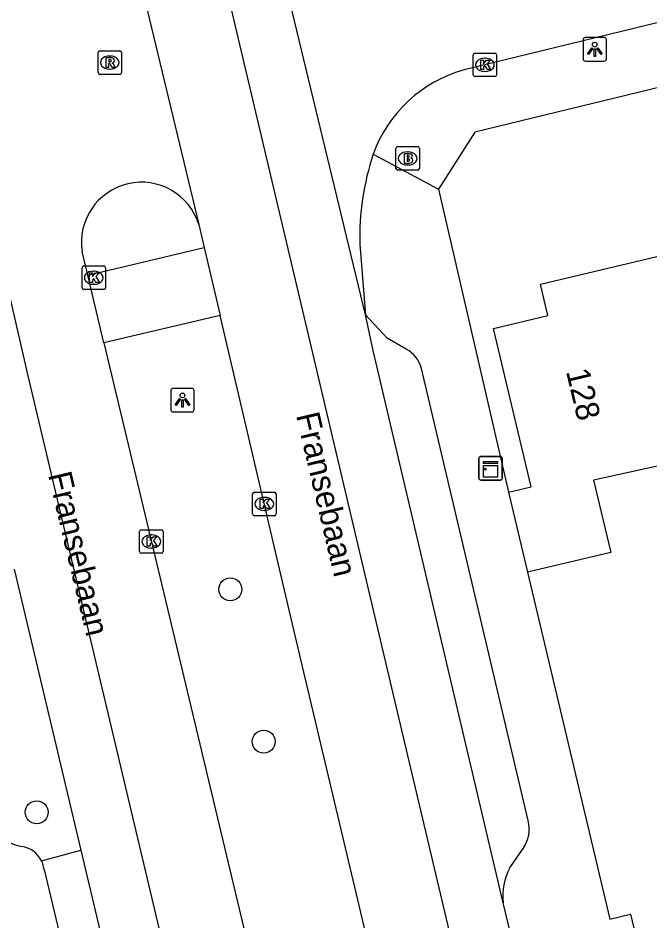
# Model space of a CAD drawing. Extents: x 158474 to 159560, y 388525 to 389605.
# Drawn here: x 159258.19 to 159285.1, y 388849.05 to 388887.46 of the extents above; entities that cross this region are included whole.
import ezdxf

# ---------------------------------------------------------------- set-up
doc = ezdxf.new("R2010")
doc.units = 0
for name, color, linetype in [('IMGEO_Boom', 7, 'Continuous'), ('IMGEO_Brandkraan', 7, 'Continuous'), ('IMGEO_Kast', 7, 'Continuous'), ('IMGEO_Kolk', 7, 'Continuous'), ('IMGEO_Lichtpunt', 7, 'Continuous'), ('IMGEO_Muur', 7, 'Continuous'), ('IMGEO_Openbare_ruimte_label', 7, 'Continuous'), ('IMGEO_Pand', 7, 'Continuous'), ('IMGEO_Pand_nummerreeks', 7, 'Continuous'), ('IMGEO_Rijbaan_lokaal_gesloten', 7, 'Continuous'), ('IMGEO_Rijbaan_lokaal_open', 7, 'Continuous'), ('IMGEO_Rioolput', 7, 'Continuous'), ('IMGEO_Verkeerseiland_groen', 7, 'Continuous'), ('IMGEO_Voetpad_open', 7, 'Continuous')]:
    doc.layers.add(name, color=color, linetype=linetype)

msp = doc.modelspace()

# ---------------------------------------------------------------- linework, layer by layer
at = {"layer": 'IMGEO_Boom'}
for centre in [(159267.227, 388863.157), (159268.651, 388856.68), (159258.987, 388853.674)]:
    msp.add_circle(centre, 0.489, dxfattribs=at)
at = {"layer": 'IMGEO_Brandkraan'}
for p, q in [((159274.282, 388881.066), (159274.282, 388881.918)), ((159274.357, 388881.992), (159275.209, 388881.992)), ((159275.283, 388881.918), (159275.283, 388881.066)), ((159274.77, 388881.772), (159274.795, 388881.772)), ((159274.793, 388881.212), (159274.768, 388881.212)), ((159275.209, 388880.992), (159274.357, 388880.992))]:
    msp.add_line(p, q, dxfattribs=at)
for points in [[(159274.282, 388881.066), (159274.282, 388881.918)], [(159274.357, 388881.992), (159275.209, 388881.992)], [(159275.283, 388881.918), (159275.283, 388881.066)], [(159274.63, 388881.692), (159274.63, 388881.292), (159274.843, 388881.292)], [(159274.861, 388881.692), (159274.63, 388881.692)], [(159274.809, 388881.611), (159274.755, 388881.611), (159274.755, 388881.535)], [(159274.755, 388881.535), (159274.808, 388881.535)], [(159274.817, 388881.459), (159274.755, 388881.459), (159274.755, 388881.378)], [(159274.755, 388881.378), (159274.817, 388881.378)], [(159275.209, 388880.992), (159274.357, 388880.992)]]:
    msp.add_lwpolyline(points, dxfattribs=at)
for centre, radius, start, end in [((159274.359, 388881.916), 0.0765, 91.552, 178.448), ((159274.359, 388881.916), 0.0765, 91.552, 178.448), ((159275.207, 388881.916), 0.0765, 1.552, 88.448), ((159275.207, 388881.916), 0.0765, 1.552, 88.448), ((159274.81, 388881.573), 0.0379, 267.8285, 90.9355), ((159274.818, 388881.418), 0.0404, 269.8759, 90.5077), ((159274.865, 388881.547), 0.145, 59.4692, 91.5367), ((159274.89, 388881.594), 0.0922, 285.5137, 58.1501), ((159274.895, 388881.402), 0.105, 301.3115, 78.989), ((159274.359, 388881.068), 0.0765, 181.552, 268.448), ((159274.359, 388881.068), 0.0765, 181.552, 268.448), ((159274.849, 388881.543), 0.251, 268.6676, 293.5347), ((159275.207, 388881.068), 0.0765, 271.552, 358.448), ((159275.207, 388881.068), 0.0765, 271.552, 358.448)]:
    msp.add_arc(centre, radius, start, end, dxfattribs=at)
for centre, major_axis, ratio, start_param, end_param in [((159274.769, 388881.492), (-0.387, 0.002), 0.722429, 4.712389, 7.853982), ((159274.794, 388881.492), (-0.39, 0.002), 0.717154, 1.570796, 4.712389)]:
    msp.add_ellipse(centre, major_axis=major_axis, ratio=ratio, start_param=start_param, end_param=end_param, dxfattribs=at)
at = {"layer": 'IMGEO_Kast'}
for p, q in [((159277.882, 388868.807), (159278.723, 388868.807)), ((159278.723, 388868.807), (159277.882, 388868.807)), ((159277.807, 388867.882), (159277.807, 388868.723)), ((159277.807, 388868.723), (159277.807, 388867.882)), ((159278.807, 388868.732), (159278.807, 388867.891)), ((159278.807, 388867.891), (159278.807, 388868.732)), ((159278.732, 388867.807), (159277.891, 388867.807)), ((159277.891, 388867.807), (159278.732, 388867.807))]:
    msp.add_line(p, q, dxfattribs=at)
for points in [[(159278.002, 388868.597), (159278.602, 388868.597), (159278.602, 388868.512), (159278.002, 388868.512), (159278.002, 388868.597)], [(159278.002, 388868.422), (159278.602, 388868.422), (159278.602, 388867.933), (159278.002, 388867.933), (159278.002, 388868.422)]]:
    msp.add_lwpolyline(points, dxfattribs=at)
msp.add_circle((159278.086, 388868.271), 0.0377, dxfattribs=at)
for centre, start, end in [((159277.885, 388868.729), 92.4484, 184.2845), ((159277.885, 388868.729), 92.4484, 184.2845), ((159278.729, 388868.729), 2.4484, 94.2845), ((159278.729, 388868.729), 2.4484, 94.2845), ((159277.885, 388867.885), 182.4484, 274.2845), ((159277.885, 388867.885), 182.4484, 274.2845), ((159278.729, 388867.885), 272.4484, 4.2845), ((159278.729, 388867.885), 272.4484, 4.2845)]:
    msp.add_arc(centre, 0.0779, start, end, dxfattribs=at)
at = {"layer": 'IMGEO_Kolk'}
for p, q in [((159277.567, 388885.043), (159277.567, 388885.895)), ((159277.642, 388885.969), (159278.494, 388885.969)), ((159278.055, 388885.749), (159278.08, 388885.749)), ((159278.568, 388885.895), (159278.568, 388885.043)), ((159278.494, 388884.969), (159277.642, 388884.969)), ((159278.078, 388885.189), (159278.053, 388885.189)), ((159260.915, 388875.99), (159260.915, 388876.842)), ((159260.99, 388876.916), (159261.842, 388876.916)), ((159261.916, 388876.842), (159261.916, 388875.99)), ((159261.403, 388876.696), (159261.428, 388876.696)), ((159261.426, 388876.136), (159261.401, 388876.136)), ((159261.842, 388875.916), (159260.99, 388875.916)), ((159268.178, 388866.365), (159268.178, 388867.217)), ((159268.253, 388867.291), (159269.105, 388867.291)), ((159269.179, 388867.217), (159269.179, 388866.365)), ((159268.666, 388867.071), (159268.691, 388867.071)), ((159268.689, 388866.511), (159268.664, 388866.511)), ((159269.105, 388866.291), (159268.253, 388866.291)), ((159263.442, 388865.693), (159264.294, 388865.693)), ((159263.367, 388864.767), (159263.367, 388865.619)), ((159263.855, 388865.473), (159263.88, 388865.473)), ((159264.368, 388865.619), (159264.368, 388864.767)), ((159263.878, 388864.913), (159263.853, 388864.913)), ((159264.294, 388864.693), (159263.442, 388864.693))]:
    msp.add_line(p, q, dxfattribs=at)
for points in [[(159277.567, 388885.043), (159277.567, 388885.895)], [(159277.642, 388885.969), (159278.494, 388885.969)], [(159277.888, 388885.669), (159278.011, 388885.669), (159278.011, 388885.518), (159278.141, 388885.669), (159278.305, 388885.669), (159278.159, 388885.518), (159278.312, 388885.269), (159278.16, 388885.269), (159278.075, 388885.433), (159278.011, 388885.366), (159278.011, 388885.269), (159277.888, 388885.269), (159277.888, 388885.669)], [(159278.568, 388885.895), (159278.568, 388885.043)], [(159278.494, 388884.969), (159277.642, 388884.969)], [(159260.915, 388875.99), (159260.915, 388876.842)], [(159260.99, 388876.916), (159261.842, 388876.916)], [(159261.916, 388876.842), (159261.916, 388875.99)], [(159261.236, 388876.616), (159261.359, 388876.616), (159261.359, 388876.465), (159261.489, 388876.616), (159261.653, 388876.616), (159261.507, 388876.465), (159261.66, 388876.216), (159261.508, 388876.216), (159261.423, 388876.38), (159261.359, 388876.313), (159261.359, 388876.216), (159261.236, 388876.216), (159261.236, 388876.616)], [(159261.842, 388875.916), (159260.99, 388875.916)], [(159268.178, 388866.365), (159268.178, 388867.217)], [(159268.253, 388867.291), (159269.105, 388867.291)], [(159269.179, 388867.217), (159269.179, 388866.365)], [(159268.499, 388866.991), (159268.622, 388866.991), (159268.622, 388866.84), (159268.752, 388866.991), (159268.916, 388866.991), (159268.77, 388866.84), (159268.923, 388866.591), (159268.771, 388866.591), (159268.686, 388866.755), (159268.622, 388866.688), (159268.622, 388866.591), (159268.499, 388866.591), (159268.499, 388866.991)], [(159269.105, 388866.291), (159268.253, 388866.291)], [(159263.442, 388865.693), (159264.294, 388865.693)], [(159263.367, 388864.767), (159263.367, 388865.619)], [(159263.688, 388865.393), (159263.811, 388865.393), (159263.811, 388865.242), (159263.941, 388865.393), (159264.105, 388865.393), (159263.959, 388865.242), (159264.112, 388864.993), (159263.96, 388864.993), (159263.875, 388865.157), (159263.811, 388865.09), (159263.811, 388864.993), (159263.688, 388864.993), (159263.688, 388865.393)], [(159264.368, 388865.619), (159264.368, 388864.767)], [(159264.294, 388864.693), (159263.442, 388864.693)]]:
    msp.add_lwpolyline(points, dxfattribs=at)
for centre, start, end in [((159277.644, 388885.893), 91.552, 178.448), ((159277.644, 388885.893), 91.552, 178.448), ((159278.492, 388885.893), 1.552, 88.448), ((159278.492, 388885.893), 1.552, 88.448), ((159277.644, 388885.045), 181.552, 268.448), ((159277.644, 388885.045), 181.552, 268.448), ((159278.492, 388885.045), 271.552, 358.448), ((159278.492, 388885.045), 271.552, 358.448), ((159260.992, 388876.84), 91.552, 178.448), ((159260.992, 388876.84), 91.552, 178.448), ((159261.84, 388876.84), 1.552, 88.448), ((159261.84, 388876.84), 1.552, 88.448), ((159260.992, 388875.992), 181.552, 268.448), ((159260.992, 388875.992), 181.552, 268.448), ((159261.84, 388875.992), 271.552, 358.448), ((159261.84, 388875.992), 271.552, 358.448), ((159268.255, 388867.215), 91.552, 178.448), ((159268.255, 388867.215), 91.552, 178.448), ((159269.103, 388867.215), 1.552, 88.448), ((159269.103, 388867.215), 1.552, 88.448), ((159268.255, 388866.367), 181.552, 268.448), ((159268.255, 388866.367), 181.552, 268.448), ((159269.103, 388866.367), 271.552, 358.448), ((159269.103, 388866.367), 271.552, 358.448), ((159263.444, 388865.617), 91.552, 178.448), ((159263.444, 388865.617), 91.552, 178.448), ((159264.292, 388865.617), 1.552, 88.448), ((159264.292, 388865.617), 1.552, 88.448), ((159263.444, 388864.769), 181.552, 268.448), ((159263.444, 388864.769), 181.552, 268.448), ((159264.292, 388864.769), 271.552, 358.448), ((159264.292, 388864.769), 271.552, 358.448)]:
    msp.add_arc(centre, 0.0765, start, end, dxfattribs=at)
for centre, major_axis, ratio, start_param, end_param in [((159278.054, 388885.469), (-0.387, 0.002), 0.722429, 4.712389, 7.853982), ((159278.079, 388885.469), (-0.39, 0.002), 0.717154, 1.570796, 4.712389), ((159261.402, 388876.416), (-0.387, 0.002), 0.722429, 4.712389, 7.853982), ((159261.427, 388876.416), (-0.39, 0.002), 0.717154, 1.570796, 4.712389), ((159268.665, 388866.791), (-0.387, 0.002), 0.722429, 4.712389, 7.853982), ((159268.69, 388866.791), (-0.39, 0.002), 0.717154, 1.570796, 4.712389), ((159263.854, 388865.193), (-0.387, 0.002), 0.722429, 4.712389, 7.853982), ((159263.879, 388865.193), (-0.39, 0.002), 0.717154, 1.570796, 4.712389)]:
    msp.add_ellipse(centre, major_axis=major_axis, ratio=ratio, start_param=start_param, end_param=end_param, dxfattribs=at)
at = {"layer": 'IMGEO_Lichtpunt'}
for p, q in [((159282.247, 388886.535), (159282.247, 388885.728)), ((159282.247, 388886.535), (159282.247, 388885.728)), ((159283.149, 388886.63), (159282.341, 388886.63)), ((159283.149, 388886.63), (159282.341, 388886.63)), ((159283.243, 388885.728), (159283.243, 388886.535)), ((159283.243, 388885.728), (159283.243, 388886.535)), ((159282.341, 388885.634), (159283.149, 388885.634)), ((159282.341, 388885.634), (159283.149, 388885.634)), ((159264.693, 388871.608), (159264.693, 388870.801)), ((159264.693, 388871.608), (159264.693, 388870.801)), ((159265.595, 388871.703), (159264.787, 388871.703)), ((159265.595, 388871.703), (159264.787, 388871.703)), ((159265.689, 388870.801), (159265.689, 388871.608)), ((159265.689, 388870.801), (159265.689, 388871.608)), ((159264.787, 388870.707), (159265.595, 388870.707)), ((159264.787, 388870.707), (159265.595, 388870.707))]:
    msp.add_line(p, q, dxfattribs=at)
for points in [[(159282.621, 388886.199), (159282.66, 388886.171), (159282.472, 388885.909), (159282.434, 388885.936), (159282.621, 388886.199)], [(159282.723, 388886.151), (159282.77, 388886.151), (159282.77, 388885.829), (159282.723, 388885.829), (159282.723, 388886.151)], [(159282.833, 388886.171), (159282.871, 388886.198), (159283.058, 388885.936), (159283.019, 388885.908), (159282.833, 388886.171)], [(159265.067, 388871.272), (159265.106, 388871.244), (159264.918, 388870.982), (159264.88, 388871.009), (159265.067, 388871.272)], [(159265.169, 388871.224), (159265.216, 388871.224), (159265.216, 388870.902), (159265.169, 388870.902), (159265.169, 388871.224)], [(159265.279, 388871.244), (159265.317, 388871.271), (159265.504, 388871.009), (159265.465, 388870.981), (159265.279, 388871.244)]]:
    msp.add_lwpolyline(points, dxfattribs=at)
for centre in [(159282.746, 388886.333), (159265.192, 388871.406)]:
    msp.add_circle(centre, 0.0994, dxfattribs=at)
for centre, start, end in [((159282.341, 388886.535), 90, 180), ((159282.341, 388886.535), 90, 180), ((159283.149, 388886.535), 0, 90), ((159283.149, 388886.535), 0, 90), ((159282.341, 388885.728), 180, 270), ((159282.341, 388885.728), 180, 270), ((159283.149, 388885.728), 270, 0), ((159283.149, 388885.728), 270, 360), ((159264.787, 388871.608), 90, 180), ((159264.787, 388871.608), 90, 180), ((159265.595, 388871.608), 0, 90), ((159265.595, 388871.608), 0, 90), ((159264.787, 388870.801), 180, 270), ((159264.787, 388870.801), 180, 270), ((159265.595, 388870.801), 270, 0), ((159265.595, 388870.801), 270, 360)]:
    msp.add_arc(centre, 0.0946, start, end, dxfattribs=at)
at = {"layer": 'IMGEO_Muur'}
msp.add_lwpolyline([(159279.877, 388863.882), (159283.385, 388849.129)], dxfattribs=at)
at = {"layer": 'IMGEO_Pand'}
for points in [[(159279.069, 388867.287), (159280.042, 388867.518), (159278.441, 388874.261), (159280.748, 388874.809), (159280.433, 388876.137), (159285.874, 388877.432)], [(159287.501, 388873.065), (159288.445, 388869.087), (159287.294, 388868.814), (159282.697, 388867.807), (159283.429, 388864.725), (159279.877, 388863.882)], [(159279.069, 388867.287), (159279.877, 388863.882)]]:
    msp.add_lwpolyline(points, dxfattribs=at)
at = {"layer": 'IMGEO_Rijbaan_lokaal_gesloten'}
for points in [[(159268.084, 388832.358), (159258.627, 388872.238), (159243.098, 388939.791), (159230.156, 389009.067), (159223.469, 389052.45)], [(159235.995, 389049.749), (159239.311, 389027.03), (159242.913, 389005.102), (159246.77, 388983.007), (159252.032, 388955.946), (159255.765, 388938.112), (159261.434, 388912.543), (159265.14, 388896.851), (159270.668, 388873.441), (159274.326, 388857.952), (159279.715, 388835.25)], [(159272.985, 388874.84), (159267.533, 388897.4)], [(159262.775, 388891.552), (159262.853, 388891.299), (159265.887, 388878.684)], [(159265.887, 388878.684), (159266.118, 388877.7)], [(159266.118, 388877.7), (159266.797, 388874.809)], [(159261.159, 388876.524), (159260.92, 388877.525)], [(159261.846, 388873.649), (159261.159, 388876.524)], [(159276.343, 388834.412), (159270.29, 388859.938), (159269.541, 388863.127), (159266.797, 388874.809)], [(159278.852, 388849.818), (159273.304, 388873.316), (159272.985, 388874.84)], [(159261.846, 388873.649), (159264.636, 388861.977), (159271.366, 388833.818), (159271.51, 388833.21)], [(159258.029, 388864.014), (159260.868, 388852.063)], [(159260.868, 388852.063), (159265.691, 388831.762), (159273.326, 388799.622), (159277.906, 388780.397), (159279.332, 388774.364)], [(159279.295, 388847.943), (159278.852, 388849.818)]]:
    msp.add_lwpolyline(points, dxfattribs=at)
msp.add_arc((159263.447, 388877.92), 2.557, 17.3942, 188.8746, dxfattribs=at)
at = {"layer": 'IMGEO_Rijbaan_lokaal_open'}
for points in [[(159297.916, 388890.323), (159277.191, 388885.255)], [(159272.742, 388877.831), (159272.985, 388874.84)], [(159259.299, 388851.238), (159262.943, 388835.991)]]:
    msp.add_lwpolyline(points, dxfattribs=at)
for centre, radius, start, end in [((159278.695, 388879.737), 5.719, 105.2454, 160.2262), ((159284.023, 388878.117), 11.284, 161.6367, 181.4521), ((159258.663, 388854.027), 1.83, 192.8448, 260.3053), ((159258.166, 388851.098), 1.141, 26.3879, 80.4689), ((159258.161, 388851.094), 1.147, 7.2039, 26.4522)]:
    msp.add_arc(centre, radius, start, end, dxfattribs=at)
at = {"layer": 'IMGEO_Rioolput'}
for p, q in [((159261.672, 388886.067), (159262.524, 388886.067)), ((159261.597, 388885.141), (159261.597, 388885.993)), ((159262.085, 388885.847), (159262.11, 388885.847)), ((159262.598, 388885.993), (159262.598, 388885.141)), ((159262.108, 388885.287), (159262.083, 388885.287)), ((159262.524, 388885.067), (159261.672, 388885.067))]:
    msp.add_line(p, q, dxfattribs=at)
for points in [[(159261.672, 388886.067), (159262.524, 388886.067)], [(159261.597, 388885.141), (159261.597, 388885.993)], [(159262.186, 388885.765), (159261.934, 388885.767), (159261.934, 388885.367)], [(159262.112, 388885.686), (159262.058, 388885.686), (159262.058, 388885.605)], [(159262.598, 388885.993), (159262.598, 388885.141)], [(159261.934, 388885.367), (159262.058, 388885.367), (159262.058, 388885.529), (159262.069, 388885.529)], [(159262.058, 388885.605), (159262.11, 388885.605)], [(159262.116, 388885.5), (159262.187, 388885.367), (159262.327, 388885.367), (159262.262, 388885.493)], [(159262.524, 388885.067), (159261.672, 388885.067)]]:
    msp.add_lwpolyline(points, dxfattribs=at)
for centre, radius, start, end in [((159261.674, 388885.991), 0.0765, 91.552, 178.448), ((159261.674, 388885.991), 0.0765, 91.552, 178.448), ((159262.522, 388885.991), 0.0765, 1.552, 88.448), ((159262.522, 388885.991), 0.0765, 1.552, 88.448), ((159262.118, 388885.59), 0.0964, 77.0061, 93.1865), ((159262.132, 388885.647), 0.0378, 276.6634, 79.6772), ((159262.185, 388885.655), 0.109, 350.3612, 89.416), ((159262.068, 388885.476), 0.0533, 26.0293, 88.6989), ((159262.094, 388885.794), 0.19, 274.7715, 282.9687), ((159262.183, 388885.655), 0.112, 277.5842, 350.9817), ((159262.167, 388885.44), 0.108, 29.5134, 73.7905), ((159261.674, 388885.143), 0.0765, 181.552, 268.448), ((159261.674, 388885.143), 0.0765, 181.552, 268.448), ((159262.522, 388885.143), 0.0765, 271.552, 358.448), ((159262.522, 388885.143), 0.0765, 271.552, 358.448)]:
    msp.add_arc(centre, radius, start, end, dxfattribs=at)
for centre, major_axis, ratio, start_param, end_param in [((159262.084, 388885.567), (-0.387, 0.002), 0.722429, 4.712389, 7.853982), ((159262.109, 388885.567), (-0.39, 0.002), 0.717154, 1.570796, 4.712389)]:
    msp.add_ellipse(centre, major_axis=major_axis, ratio=ratio, start_param=start_param, end_param=end_param, dxfattribs=at)
at = {"layer": 'IMGEO_Verkeerseiland_groen'}
msp.add_lwpolyline([(159259.188, 388851.605), (159260.868, 388852.063)], dxfattribs=at)
at = {"layer": 'IMGEO_Voetpad_open'}
for points in [[(159353.95, 388891.736), (159353.66, 388892.956), (159336.429, 388903.595), (159307.04, 388896.602), (159302.591, 388888.674), (159277.636, 388882.603), (159276.089, 388880.176)], [(159273.313, 388881.672), (159276.089, 388880.176)], [(159276.089, 388880.176), (159279.069, 388867.287)], [(159261.159, 388876.524), (159266.118, 388877.7)], [(159266.797, 388874.809), (159261.846, 388873.649)], [(159274.723, 388873.376), (159273.909, 388873.839), (159272.985, 388874.84)], [(159279.912, 388853.321), (159275.371, 388872.557)], [(159279.877, 388863.882), (159283.385, 388849.129), (159284.273, 388849.344), (159287.179, 388837.107)], [(159279.133, 388851.312), (159279.695, 388852.135)]]:
    msp.add_lwpolyline(points, dxfattribs=at)
for centre, radius, start, end in [((159274.091, 388872.21), 1.326, 15.162, 61.5407), ((159278.511, 388852.964), 1.446, 324.9836, 14.2792), ((159281.246, 388850.141), 2.416, 151.0117, 187.6842)]:
    msp.add_arc(centre, radius, start, end, dxfattribs=at)

# ---------------------------------------------------------------- texts
at = {"layer": 'IMGEO_Openbare_ruimte_label'}
for rotation, p in [(283.2996, (159270.021, 388870.569)), (283.3553, (159259.465, 388868.039))]:
    msp.add_text('Fransebaan', height=1, rotation=rotation, dxfattribs=at).set_placement(p)
at = {"layer": 'IMGEO_Pand_nummerreeks'}
msp.add_text('128', height=1, rotation=283.4857, dxfattribs=at).set_placement((159281.515, 388872.435))

doc.saveas('drawing.dxf')
